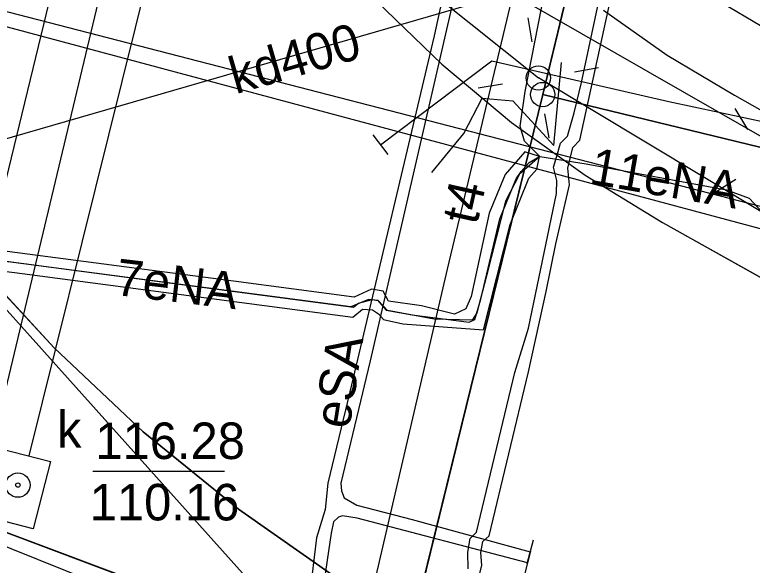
# Model space of a CAD drawing. Extents: x 6424617 to 6425697, y 5665845 to 5667190.
# Drawn here: x 6425514.37 to 6425529.5, y 5666947.39 to 5666958.69 of the extents above; entities that cross this region are included whole.
import ezdxf

# ---------------------------------------------------------------- set-up
doc = ezdxf.new("R2010")
doc.units = 0
for name, color, linetype in [('Warstwa 1', 7, 'Continuous'), ('Warstwa 10', 7, 'Continuous'), ('Warstwa 11', 7, 'Continuous'), ('Warstwa 12', 7, 'Continuous'), ('Warstwa 13', 7, 'Continuous'), ('Warstwa 14', 7, 'Continuous'), ('Warstwa 15', 7, 'Continuous'), ('Warstwa 16', 7, 'Continuous'), ('Warstwa 2', 7, 'Continuous'), ('Warstwa 20', 7, 'Continuous'), ('Warstwa 23', 7, 'Continuous'), ('Warstwa 4', 7, 'Continuous'), ('Warstwa 5', 7, 'Continuous'), ('Warstwa 6', 7, 'Continuous'), ('Warstwa 61', 7, 'Continuous'), ('Warstwa 8', 7, 'Continuous'), ('Warstwa 9', 7, 'Continuous')]:
    doc.layers.add(name, color=color, linetype=linetype)

msp = doc.modelspace()

# ---------------------------------------------------------------- linework, layer by layer
at = {"layer": 'Warstwa 1'}
for p, q in [((6425525.198, 5666957.05), (6425527.303, 5666965.745)), ((6425525.198, 5666957.05), (6425527.303, 5666965.745)), ((6425522.252, 5666945.035), (6425525.198, 5666957.05)), ((6425522.252, 5666945.035), (6425525.198, 5666957.05)), ((6425525.198, 5666957.05), (6425544.583, 5666952.346)), ((6425525.198, 5666957.05), (6425544.583, 5666952.346)), ((6425496.12, 5666954.85), (6425522.252, 5666945.035)), ((6425496.12, 5666954.85), (6425522.252, 5666945.035))]:
    msp.add_line(p, q, dxfattribs=at)
at = {"layer": 'Warstwa 10'}
for points in [[(6425536.147, 5667012.755), (6425534.484, 5667006.063), (6425533.074, 5667000.347), (6425532.785, 5666998.949), (6425531.703, 5666994.572), (6425530.742, 5666990.523), (6425529.721, 5666986.474), (6425527.953, 5666979.513), (6425526.809, 5666974.703), (6425525.742, 5666970.261), (6425525.204, 5666968.279), (6425524.224, 5666964.008), (6425522.97, 5666958.257), (6425521.24, 5666950.949), (6425520.79, 5666949.075), (6425520.74, 5666948.532), (6425520.561, 5666947.948), (6425520.419, 5666946.763), (6425520.147, 5666945.508), (6425519.516, 5666941.753), (6425519.079, 5666939.942), (6425519.107, 5666939.798), (6425519.373, 5666939.457)], [(6425535.06, 5667006.36), (6425534.21, 5667005.96), (6425527.47, 5667006.87), (6425521.11, 5667008.02), (6425511.65, 5667010.69), (6425511.04, 5667010.12), (6425510.23, 5667005.12), (6425507.8, 5666997.47), (6425502.22, 5666979.23), (6425499.7, 5666975.32), (6425496.98, 5666963.87), (6425497.18, 5666963.16), (6425549.77, 5666949.56), (6425554.77, 5666947.54), (6425572.63, 5666943.55), (6425574.23, 5666942.49)], [(6425535.06, 5667006.36), (6425533.782, 5667001.186), (6425532.796, 5666997.407), (6425531.921, 5666993.671), (6425530.216, 5666987.252), (6425528.536, 5666980.632), (6425527.034, 5666974.396), (6425525.187, 5666966.894), (6425523.244, 5666958.476), (6425521.661, 5666951.585), (6425521.061, 5666949.07), (6425521.073, 5666948.913), (6425521.128, 5666948.769), (6425521.385, 5666948.623), (6425522.524, 5666948.324), (6425524.939, 5666947.661)], [(6425523.673, 5666947.315), (6425523.662, 5666947.655), (6425523.709, 5666947.938), (6425523.838, 5666948.065), (6425524.63, 5666951.347), (6425524.909, 5666952.257), (6425525.481, 5666955.017), (6425525.485, 5666955.287), (6425525.417, 5666955.557), (6425525.491, 5666955.783), (6425525.565, 5666956.052), (6425525.709, 5666956.192), (6425525.842, 5666956.673), (6425525.992, 5666957.296), (6425527.418, 5666963.964)], [(6425524.887, 5666947.437), (6425521.393, 5666948.356), (6425521.094, 5666948.403), (6425521.008, 5666948.375), (6425520.906, 5666948.276), (6425520.861, 5666948.049), (6425520.69, 5666946.892), (6425520.311, 5666945.084), (6425519.739, 5666941.564), (6425519.29, 5666939.595), (6425519.373, 5666939.457)]]:
    msp.add_lwpolyline(points, dxfattribs=at)
msp.add_circle((6425525.198, 5666957.05), 0.25, dxfattribs=at)
at = {"layer": 'Warstwa 12'}
for points in [[(6425523.101, 5667015.68), (6425523.09, 5667015.65), (6425520.96, 5667005.56), (6425519.59, 5666997.17), (6425517.95, 5666989.63), (6425516.66, 5666982.82), (6425515.78, 5666975.38), (6425516.65, 5666969.82), (6425519.41, 5666963.59), (6425522.98, 5666959.1), (6425525.11, 5666957.39)], [(6425512.924, 5666950.076), (6425516.344, 5666964.168), (6425518.583, 5666973.482), (6425525.425, 5667002.06)], [(6425527.066, 5667001.642), (6425520.141, 5666972.042), (6425517.928, 5666962.804), (6425514.661, 5666949.631)], [(6425572.643, 5666928.419), (6425556.94, 5666940.57), (6425551.95, 5666943.95), (6425546.71, 5666946.98), (6425541.46, 5666949.92), (6425536.23, 5666952.43), (6425523.28, 5666959.86), (6425523.62, 5666962.92), (6425525.26, 5666969.55), (6425525.912, 5666975.56)], [(6425553.71, 5666947.2), (6425549.6, 5666948.95), (6425497.24, 5666962.99), (6425496.43, 5666962.29), (6425494.49, 5666954.59), (6425489.02, 5666931.76), (6425484.64, 5666933.61), (6425476.81, 5666937.15), (6425438.84, 5666952.53), (6425435.57, 5666952.21), (6425429.97, 5666954.78), (6425402.11, 5666966.81), (6425387.27, 5666972.4), (6425380.77, 5666966.54), (6425363.64, 5666950.72), (6425363.13, 5666950.36), (6425362.37, 5666949.84), (6425357.72, 5666956.9), (6425346.14, 5666972.82)], [(6425518.543, 5666931.101), (6425518.43, 5666932.463), (6425518.594, 5666933.379), (6425520.72, 5666942.726), (6425521.392, 5666945.492), (6425523.246, 5666953.467), (6425525.5, 5666962.935), (6425526.159, 5666965.802)], [(6425533.04, 5666940.926), (6425528.311, 5666942.214), (6425526.069, 5666942.766), (6425525.221, 5666943.046), (6425524.782, 5666943.15), (6425524.375, 5666943.467), (6425524.151, 5666943.783), (6425523.915, 5666944.282), (6425523.696, 5666944.909), (6425523.659, 5666945.364), (6425523.624, 5666945.974), (6425523.73, 5666946.526), (6425523.953, 5666947.382), (6425523.928, 5666947.652), (6425523.973, 5666947.878), (6425524.102, 5666947.99), (6425524.91, 5666951.358), (6425525.269, 5666953.007), (6425525.465, 5666953.983), (6425525.75, 5666955.197), (6425525.711, 5666955.538), (6425525.816, 5666955.962), (6425525.96, 5666956.116), (6425527.505, 5666963.196)], [(6425503.4, 5666953.02), (6425503.88, 5666953.16), (6425505.02, 5666953.49), (6425509.92, 5666954.91), (6425531.65, 5666961.2)], [(6425525.142, 5666955.779), (6425524.824, 5666956.092), (6425524.733, 5666956.403), (6425524.837, 5666957.115), (6425525.243, 5666959.18)], [(6425521.875, 5666956.02), (6425524.156, 5666957.742), (6425527.787, 5666956.908), (6425531.886, 5666956.029), (6425555.419, 5666950.245), (6425576.407, 5666945.204)], [(6425525.425, 5666956.007), (6425525.586, 5666957.705)], [(6425572.344, 5666927.084), (6425571.98, 5666927.19), (6425559.63, 5666937.31), (6425551.37, 5666942.38), (6425534.13, 5666951.97), (6425525.11, 5666957.39)], [(6425522.928, 5666955.447), (6425523.578, 5666956.249), (6425523.957, 5666956.975), (6425524.586, 5666956.917), (6425525.425, 5666956.007)], [(6425525.142, 5666955.779), (6425524.721, 5666955.417), (6425524.435, 5666954.863), (6425524.049, 5666953.33), (6425523.85, 5666952.572), (6425523.75, 5666952.421), (6425522.976, 5666952.442), (6425522.014, 5666952.619), (6425521.826, 5666952.825), (6425521.623, 5666952.84), (6425521.266, 5666952.692), (6425515.333, 5666953.475), (6425510.685, 5666954.089), (6425510.037, 5666954.071), (6425509.681, 5666953.949), (6425509.272, 5666953.7), (6425508.932, 5666953.152), (6425508.505, 5666952.009), (6425507.216, 5666945.468), (6425503.204, 5666927.223), (6425497.683, 5666902.344), (6425491.319, 5666877.188)], [(6425525.142, 5666955.779), (6425526.092, 5666955.628), (6425528.965, 5666955.097), (6425529.433, 5666954.926), (6425529.821, 5666954.503), (6425531.206, 5666951.761), (6425531.134, 5666951.165), (6425531.033, 5666950.808)]]:
    msp.add_lwpolyline(points, dxfattribs=at)
at = {"layer": 'Warstwa 14'}
msp.add_line((6425515.97, 5666949.317), (6425518.674, 5666949.317), dxfattribs=at)
msp.add_circle((6425514.435, 5666949.033), 0.045, dxfattribs=at)
at = {"layer": 'Warstwa 16'}
msp.add_lwpolyline([(6425512.727, 5666950.127), (6425515.102, 5666949.518), (6425514.748, 5666948.139), (6425512.373, 5666948.748)], close=True, dxfattribs=at)
at = {"layer": 'Warstwa 2'}
msp.add_lwpolyline([(6425569.428, 5666914.078), (6425559.167, 5666924.494), (6425550.651, 5666930.93), (6425537.233, 5666937.954), (6425528.275, 5666942.097), (6425504.759, 5666951.565), (6425481.965, 5666960.63)], dxfattribs=at)
msp.add_circle((6425525.11, 5666957.39), 0.25, dxfattribs=at)
at = {"layer": 'Warstwa 20'}
for p, q in [((6425522.026, 5666955.82), (6425521.724, 5666956.22)), ((6425525.005, 5666947.902), (6425524.873, 5666947.42)), ((6425524.951, 5666947.679), (6425524.823, 5666947.195))]:
    msp.add_line(p, q, dxfattribs=at)
at = {"layer": 'Warstwa 23'}
msp.add_lwpolyline([(6425511.499, 5666955.639), (6425524.698, 5666940.911)], dxfattribs=at)
at = {"layer": 'Warstwa 4'}
for points in [[(6425524.982, 5666958.129), (6425524.897, 5666958.622)], [(6425525.849, 5666957.518), (6425526.342, 5666957.603)], [(6425524.371, 5666957.262), (6425523.878, 5666957.177)], [(6425525.238, 5666956.651), (6425525.323, 5666956.158)], [(6425529.408, 5666956.334), (6425529.146, 5666956.76)], [(6425529.161, 5666955.303), (6425528.735, 5666955.041)]]:
    msp.add_lwpolyline(points, dxfattribs=at)
msp.add_circle((6425514.435, 5666949.033), 0.25, dxfattribs=at)
at = {"layer": 'Warstwa 6'}
for points in [[(6425511.35, 5667018.315), (6425496.12, 5666954.85), (6425522.252, 5666945.035), (6425525.198, 5666957.05), (6425527.303, 5666965.745), (6425538.589, 5667012.208)], [(6425578.242, 5666953.39), (6425576.814, 5666953.737), (6425527.303, 5666965.745), (6425525.198, 5666957.05), (6425544.583, 5666952.346), (6425576.283, 5666944.651)], [(6425521.792, 5666958.965), (6425523.129, 5666957.67), (6425524.557, 5666956.477), (6425526.07, 5666955.393), (6425527.658, 5666954.423), (6425550.217, 5666941.781), (6425552.369, 5666940.535), (6425554.487, 5666939.233), (6425556.571, 5666937.877), (6425558.618, 5666936.466), (6425560.628, 5666935.003), (6425562.599, 5666933.488), (6425564.53, 5666931.922), (6425566.419, 5666930.305), (6425568.266, 5666928.641), (6425569.097, 5666927.921), (6425569.979, 5666927.264), (6425570.907, 5666926.674), (6425571.876, 5666926.153), (6425572.112, 5666926.048)], [(6425474.6, 5666748.65), (6425522.252, 5666945.035), (6425496.12, 5666954.85), (6425495.139, 5666950.762), (6425471.236, 5666853.116), (6425454.155, 5666782.149)], [(6425569.746, 5666915.495), (6425568.382, 5666917.097), (6425565.533, 5666920.131), (6425562.542, 5666923.024), (6425559.413, 5666925.769), (6425556.156, 5666928.36), (6425552.926, 5666930.499), (6425549.645, 5666932.56), (6425546.315, 5666934.54), (6425542.938, 5666936.439), (6425539.517, 5666938.256), (6425536.052, 5666939.99), (6425532.546, 5666941.639), (6425529.002, 5666943.202), (6425525.421, 5666944.68), (6425523.176, 5666945.81), (6425521.018, 5666947.099), (6425518.958, 5666948.54), (6425517.007, 5666950.126), (6425515.176, 5666951.849), (6425513.474, 5666953.698)]]:
    msp.add_lwpolyline(points, dxfattribs=at)
msp.add_lwpolyline([(6425525.198, 5666957.05), (6425522.252, 5666945.035), (6425527.109, 5666943.856), (6425541.648, 5666940.33), (6425544.583, 5666952.346)], close=True, dxfattribs=at)
at = {"layer": 'Warstwa 61'}
for points in [[(6425481.038, 5666812.596), (6425491.4, 5666857.132), (6425513.738, 5666949.133), (6425526.476, 5667002.476), (6425529.291, 5667014.292)], [(6425512.373, 5666953.863), (6425514.551, 5666953.579), (6425518.832, 5666953.014), (6425521.318, 5666952.688), (6425521.418, 5666952.769), (6425521.698, 5666952.842), (6425521.818, 5666952.821), (6425521.987, 5666952.622), (6425522.519, 5666952.527), (6425523.69, 5666952.379), (6425523.805, 5666952.435), (6425523.931, 5666952.852), (6425524.319, 5666954.499), (6425524.652, 5666955.32), (6425524.755, 5666955.467), (6425524.918, 5666955.653), (6425525.136, 5666955.78)]]:
    msp.add_lwpolyline(points, dxfattribs=at)
at = {"layer": 'Warstwa 8'}
for p, q in [((6425521.792, 5666958.965), (6425523.129, 5666957.67)), ((6425523.129, 5666957.67), (6425524.557, 5666956.477)), ((6425524.557, 5666956.477), (6425526.07, 5666955.393)), ((6425526.07, 5666955.393), (6425527.658, 5666954.423)), ((6425527.658, 5666954.423), (6425550.217, 5666941.781)), ((6425513.474, 5666953.698), (6425515.176, 5666951.849)), ((6425515.176, 5666951.849), (6425517.007, 5666950.126)), ((6425517.007, 5666950.126), (6425518.958, 5666948.54)), ((6425518.958, 5666948.54), (6425521.018, 5666947.099))]:
    msp.add_line(p, q, dxfattribs=at)
for points in [[(6425512.346, 5666953.658), (6425514.524, 5666953.377), (6425521.307, 5666952.482), (6425521.506, 5666952.643), (6425521.709, 5666952.628), (6425521.834, 5666952.55), (6425521.935, 5666952.434), (6425522.327, 5666952.341), (6425523.987, 5666952.219), (6425524.534, 5666954.384), (6425524.913, 5666955.331), (6425525.078, 5666955.515), (6425525.136, 5666955.78), (6425524.829, 5666955.874), (6425524.43, 5666955.409), (6425524.103, 5666954.613), (6425523.728, 5666952.903), (6425523.623, 5666952.65), (6425523.393, 5666952.539), (6425522.71, 5666952.712), (6425522.038, 5666952.81), (6425521.927, 5666953.014), (6425521.686, 5666953.055), (6425521.329, 5666952.894), (6425518.859, 5666953.216), (6425511.546, 5666954.18)], [(6425525.142, 5666955.779), (6425526.092, 5666955.628), (6425528.965, 5666955.097), (6425529.433, 5666954.926), (6425529.821, 5666954.503), (6425531.206, 5666951.761), (6425531.134, 5666951.165), (6425531.033, 5666950.808)]]:
    msp.add_lwpolyline(points, dxfattribs=at)
at = {"layer": 'Warstwa 9'}
for p, q in [((6425528.568, 5666959.12), (6425529.849, 5666958.354)), ((6425526.445, 5666958.782), (6425527.753, 5666957.861)), ((6425527.753, 5666957.861), (6425529.129, 5666957.035)), ((6425529.129, 5666957.035), (6425551.666, 5666944.405))]:
    msp.add_line(p, q, dxfattribs=at)

# ---------------------------------------------------------------- texts
at = {"layer": 'Warstwa 11'}
msp.add_text('eSA', height=0.75, rotation=81.1652, dxfattribs=at).set_placement((6425521.232, 5666950.168))
at = {"layer": 'Warstwa 13'}
for s, rotation, p in [('kd400', 16.146, (6425518.9, 5666957.053)), ('11eNA', 350.2262, (6425526.133, 5666955.225)), ('t4', 77.3035, (6425523.849, 5666954.355)), ('7eNA', 353.1769, (6425516.41, 5666952.94))]:
    msp.add_text(s, height=0.75, rotation=rotation, dxfattribs=at).set_placement(p)
at = {"layer": 'Warstwa 14'}
msp.add_text('110.16', height=0.75, dxfattribs=at).set_placement((6425515.909, 5666948.308))
at = {"layer": 'Warstwa 15'}
msp.add_text('116.28', height=0.75, dxfattribs=at).set_placement((6425516.025, 5666949.568))
at = {"layer": 'Warstwa 5'}
msp.add_text('k', height=0.75, dxfattribs=at).set_placement((6425515.238, 5666949.803))

doc.saveas('drawing.dxf')
